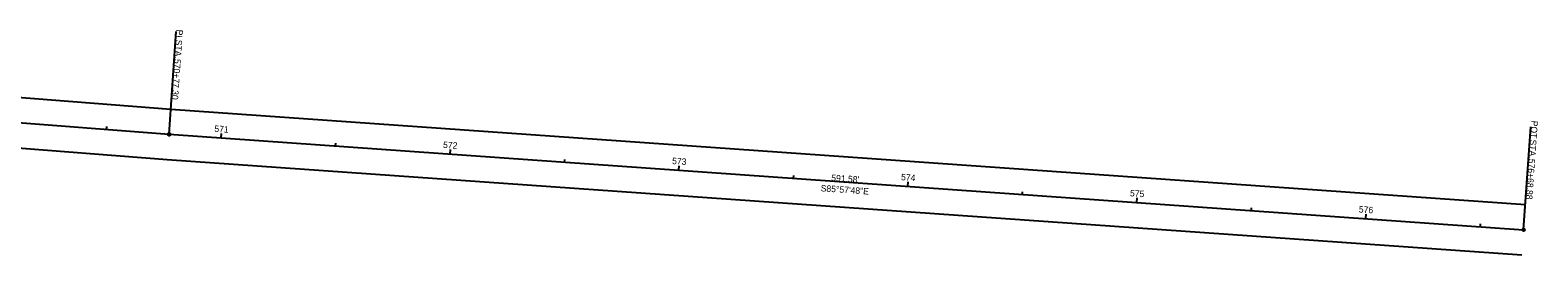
# Model space of a CAD drawing. Extents: x 1898481 to 1901152, y 703119 to 703373.
# Drawn here: x 1900495 to 1901152, y 703119 to 703218 of the extents above; entities that cross this region are included whole.
import ezdxf

# ---------------------------------------------------------------- set-up
doc = ezdxf.new("R2010")
doc.units = 0
for name, color, linetype in [('_CIVIL_CONSTRUCTION', 7, 'Continuous'), ('DT_P_Terrain_Boundary', 7, 'Continuous'), ('DT_P_Triangles', 7, 'Continuous'), ('PF_X_Ground_Line', 7, 'Continuous'), ('PV_P_EOP', 7, 'Continuous'), ('SC_Scratch1', 7, 'Continuous')]:
    doc.layers.add(name, color=color, linetype=linetype)

msp = doc.modelspace()

# ---------------------------------------------------------------- linework, layer by layer
at = {"layer": '_CIVIL_CONSTRUCTION'}
for p, q in [((1900555.26, 703172.1), (1900558.43, 703216.99)), ((1901145.37, 703130.46), (1901148.54, 703175.35))]:
    msp.add_line(p, q, dxfattribs=at)
for centre in [(1900555.26, 703172.1), (1901145.37, 703130.46)]:
    msp.add_circle(centre, 0.6, dxfattribs=at)
at = {"layer": 'DT_P_Triangles'}
for p, q in [((1900528.04, 703174.25), (1900528.14, 703175.44)), ((1900577.9, 703170.51), (1900578.04, 703172.5)), ((1900627.78, 703166.99), (1900627.86, 703168.18)), ((1900677.66, 703163.47), (1900677.8, 703165.46)), ((1900727.53, 703159.95), (1900727.62, 703161.14)), ((1900777.41, 703156.43), (1900777.55, 703158.42)), ((1900827.28, 703152.91), (1900827.37, 703154.1)), ((1900877.16, 703149.39), (1900877.3, 703151.38)), ((1900927.04, 703145.87), (1900927.12, 703147.06)), ((1900976.91, 703142.35), (1900977.05, 703144.34)), ((1901026.79, 703138.83), (1901026.87, 703140.02)), ((1901076.66, 703135.31), (1901076.8, 703137.3)), ((1901126.54, 703131.79), (1901126.62, 703132.98))]:
    msp.add_line(p, q, dxfattribs=at)
at = {"layer": 'PV_P_EOP'}
for p, q in [((1900168.38, 703213.58), (1900556.08, 703183.07)), ((1900166.74, 703191.64), (1900554.44, 703161.13)), ((1900556.08, 703183.07), (1901146.14, 703141.43)), ((1900554.44, 703161.13), (1901144.6, 703119.49))]:
    msp.add_line(p, q, dxfattribs=at)
at = {"layer": 'SC_Scratch1'}
for p, q in [((1900167.56, 703202.61), (1900555.26, 703172.1)), ((1900555.26, 703172.1), (1901145.37, 703130.46))]:
    msp.add_line(p, q, dxfattribs=at)

# ---------------------------------------------------------------- texts
at = {"layer": '_CIVIL_CONSTRUCTION'}
for s, p in [('PI', (1900558.53, 703217.88)), (' STA. ', (1900558.29, 703214.5)), ('570+77.30', (1900557.63, 703205.07)), ('POT', (1901148.78, 703178.12)), (' STA. ', (1901148.27, 703170.94)), ('576+68.88', (1901147.6, 703161.51))]:
    msp.add_text(s, height=2.8, rotation=265.96323, dxfattribs=at).set_placement(p)
at = {"layer": 'DT_P_Terrain_Boundary'}
msp.add_text("591.58'", height=2.8, rotation=355.96323, dxfattribs=at).set_placement((1900843.65, 703151.79))
at = {"layer": 'DT_P_Triangles'}
for s, p in [('571', (1900574.94, 703173.22)), ('572', (1900674.56, 703166.19)), ('573', (1900774.32, 703159.15)), ('574', (1900874.07, 703152.11)), ('575', (1900973.79, 703145.07)), ('576', (1901073.49, 703138.04))]:
    msp.add_text(s, height=2.8, rotation=355.96323, dxfattribs=at).set_placement(p)
at = {"layer": 'PF_X_Ground_Line'}
msp.add_text('S85°57\'48"E', height=2.8, rotation=355.96323, dxfattribs=at).set_placement((1900839.06, 703147.26))

doc.saveas('drawing.dxf')
